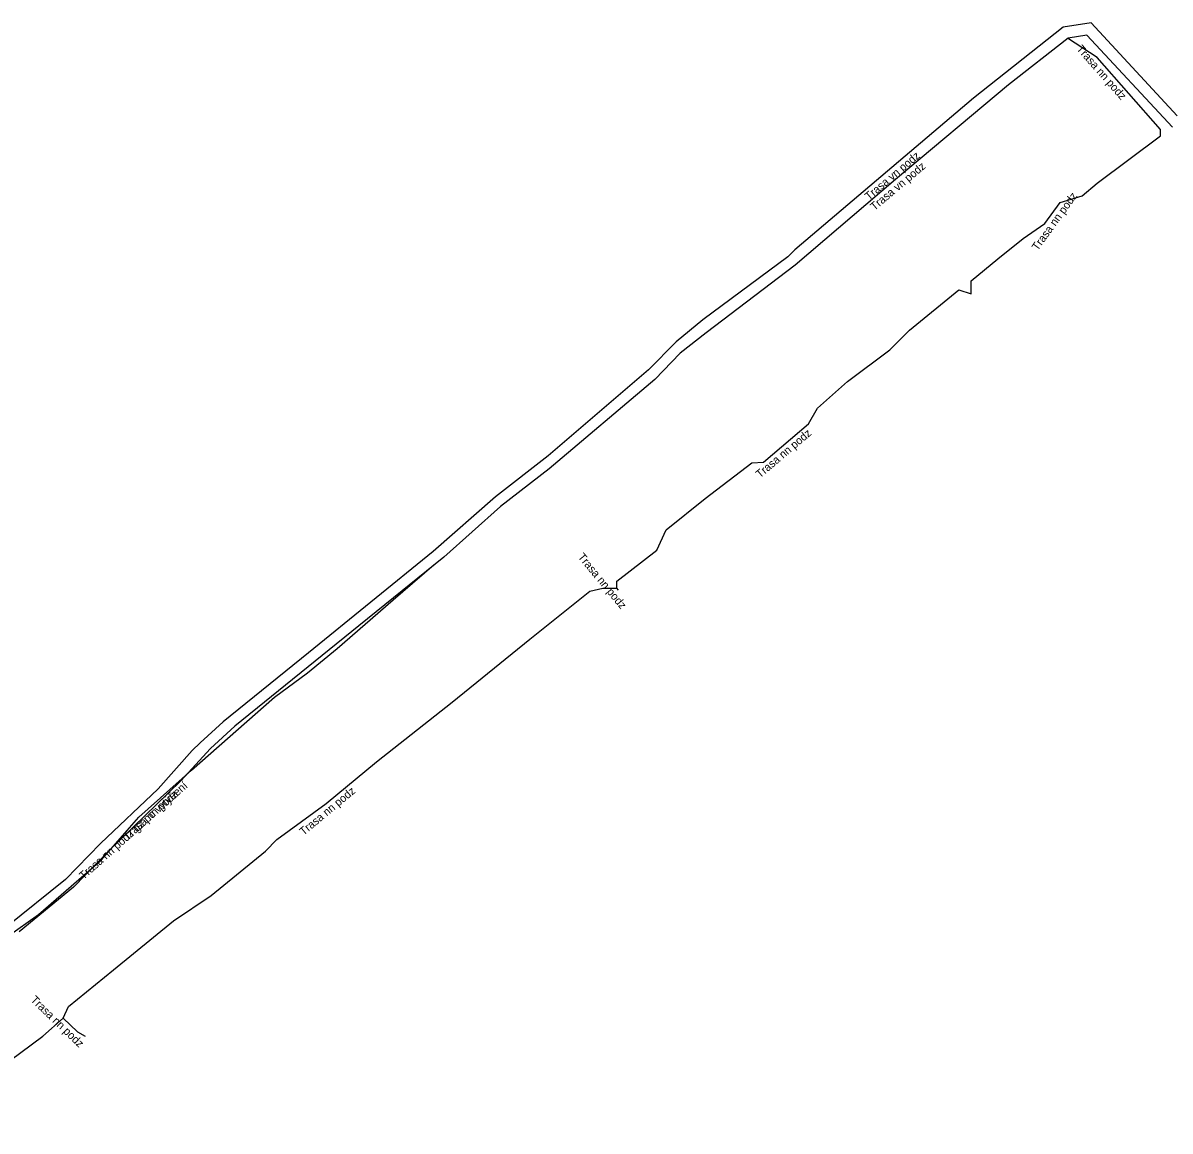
# Model space of a CAD drawing. Extents: x -703240 to -702678, y -1007635 to -1007322.
# Drawn here: x -702830.5 to -702758.8, y -1007470.7 to -1007401.5 of the extents above; entities that cross this region are included whole.
import ezdxf

# ---------------------------------------------------------------- set-up
doc = ezdxf.new("R2010")
doc.units = 0
for name, color, linetype in [('Popiskový text - Ostatní atributy Trasy', 7, 'Continuous'), ('Spojnice NN', 7, 'Continuous'), ('Spojnice VN', 7, 'Continuous')]:
    doc.layers.add(name, color=color, linetype=linetype)

msp = doc.modelspace()

# ---------------------------------------------------------------- linework, layer by layer
at = {"layer": 'Spojnice NN'}
for points in [[(-702759.41, -1007408.15), (-702763.37, -1007403.66), (-702765.23, -1007402.45)], [(-702771.25, -1007418.43), (-702771.25, -1007417.61), (-702769.58, -1007416.23), (-702767.99, -1007414.97), (-702766.64, -1007414.03), (-702765.69, -1007412.72), (-702764.31, -1007412.29), (-702763.36, -1007411.5), (-702759.41, -1007408.54), (-702759.41, -1007408.15)], [(-702793.39, -1007436.82), (-702793.39, -1007436.38), (-702790.89, -1007434.43), (-702790.31, -1007433.16), (-702787.86, -1007431.2), (-702784.95, -1007428.98), (-702784.23, -1007428.93), (-702781.41, -1007426.54), (-702780.84, -1007425.56), (-702778.98, -1007423.9), (-702776.33, -1007421.91), (-702775.1, -1007420.69), (-702772.01, -1007418.16), (-702771.25, -1007418.43)], [(-702839.14, -1007464.79), (-702836.99, -1007462.74), (-702833.42, -1007459.94), (-702829.52, -1007457.19), (-702825.59, -1007453.79), (-702823.26, -1007451.11), (-702819.97, -1007448.18), (-702814.78, -1007443.62), (-702812.71, -1007442.11), (-702810.87, -1007440.57), (-702807.36, -1007437.54), (-702804.792, -1007435.331)], [(-702839.14, -1007464.79), (-702836.99, -1007462.74), (-702833.42, -1007459.94), (-702829.52, -1007457.19), (-702825.59, -1007453.79), (-702823.26, -1007451.11), (-702819.97, -1007448.18), (-702814.78, -1007443.62), (-702812.71, -1007442.11), (-702810.87, -1007440.57), (-702807.36, -1007437.54), (-702804.792, -1007435.331)], [(-702827.98, -1007463.68), (-702827.66, -1007462.94), (-702824.83, -1007460.65), (-702821.09, -1007457.6), (-702818.73, -1007456.01), (-702815.34, -1007453.24), (-702814.64, -1007452.52), (-702811.55, -1007450.27), (-702808.41, -1007447.66), (-702803.67, -1007443.93), (-702798.83, -1007439.99), (-702795.08, -1007436.99), (-702794.27, -1007436.81), (-702793.39, -1007436.82)], [(-702793.287, -1007436.944), (-702793.39, -1007436.82)], [(-702836.43, -1007470.73), (-702835.75, -1007470.17), (-702834.13, -1007468.4), (-702829.26, -1007464.8), (-702827.98, -1007463.68)], [(-702827.98, -1007463.68), (-702827.09, -1007464.54), (-702826.608, -1007464.8)]]:
    msp.add_lwpolyline(points, dxfattribs=at)
at = {"layer": 'Spojnice VN'}
for points in [[(-702758.367, -1007407.299), (-702763.741, -1007401.495), (-702765.494, -1007401.762), (-702771.09, -1007406.205), (-702782.255, -1007415.675), (-702782.698, -1007416.113), (-702788.01, -1007420.05), (-702789.682, -1007421.418), (-702791.416, -1007423.17), (-702793.451, -1007424.916), (-702797.685, -1007428.545), (-702800.957, -1007431.094), (-702804.866, -1007434.519), (-702812.661, -1007440.849), (-702817.989, -1007445.158), (-702819.415, -1007446.472), (-702819.915, -1007446.946), (-702822.053, -1007449.345), (-702825.655, -1007452.77), (-702827.827, -1007455.01), (-702831.56, -1007458.012)], [(-702758.663, -1007408.001), (-702764.016, -1007402.254), (-702765.191, -1007402.444), (-702768.918, -1007405.37), (-702775.963, -1007411.285), (-702782.231, -1007416.622), (-702787.811, -1007420.86), (-702789.429, -1007422.135), (-702791.007, -1007423.77), (-702797.604, -1007429.354), (-702800.647, -1007431.714), (-702804.186, -1007434.867), (-702809.517, -1007439.164), (-702817.251, -1007445.435), (-702818.772, -1007446.822), (-702820.637, -1007448.853), (-702825.1, -1007453.206), (-702827.331, -1007455.484), (-702830.736, -1007458.277)]]:
    msp.add_lwpolyline(points, dxfattribs=at)

# ---------------------------------------------------------------- texts
at = {"layer": 'Popiskový text - Ostatní atributy Trasy'}
for s, rotation, p in [('Trasa nn podz', 311.411, (-702764.694, -1007403.142)), ('Trasa vn podz', 40.30415, (-702777.627, -1007412.602)), ('Trasa vn podz', 40.01691, (-702777.289, -1007413.246)), ('Trasa nn podz', 54.05072, (-702767.091, -1007415.76)), ('Trasa nn podz', 40.28187, (-702784.44, -1007429.96)), ('Trasa nn podz', 309.71455, (-702795.85, -1007434.876)), ('Trasa nn podz gz po vytýèení', 41.68754, (-702826.708, -1007455.051)), ('Trasa nn podz', 41.68754, (-702823.956, -1007452.6)), ('Trasa nn podz', 39.7337, (-702812.961, -1007452.288)), ('Trasa nn podz', 315.98212, (-702830.053, -1007462.581))]:
    msp.add_text(s, height=0.5, rotation=rotation, dxfattribs=at).set_placement(p)

doc.saveas('drawing.dxf')
